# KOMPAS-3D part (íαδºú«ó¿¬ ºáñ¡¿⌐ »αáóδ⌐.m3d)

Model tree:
1. Эскиз:2
2. Операция выдавливания:1
     Расстояние 1 = 43; Расстояние 2 = 1.7
3. Эскиз:4
4. Вырезать элемент выдавливания:2
     Расстояние 1 = 41
5. Скругление:3
     Радиус = 3
6. Скругление:4
     Радиус = 3

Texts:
  брызговик задний правый
  Полипропилен  ГОСТ 26996-86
